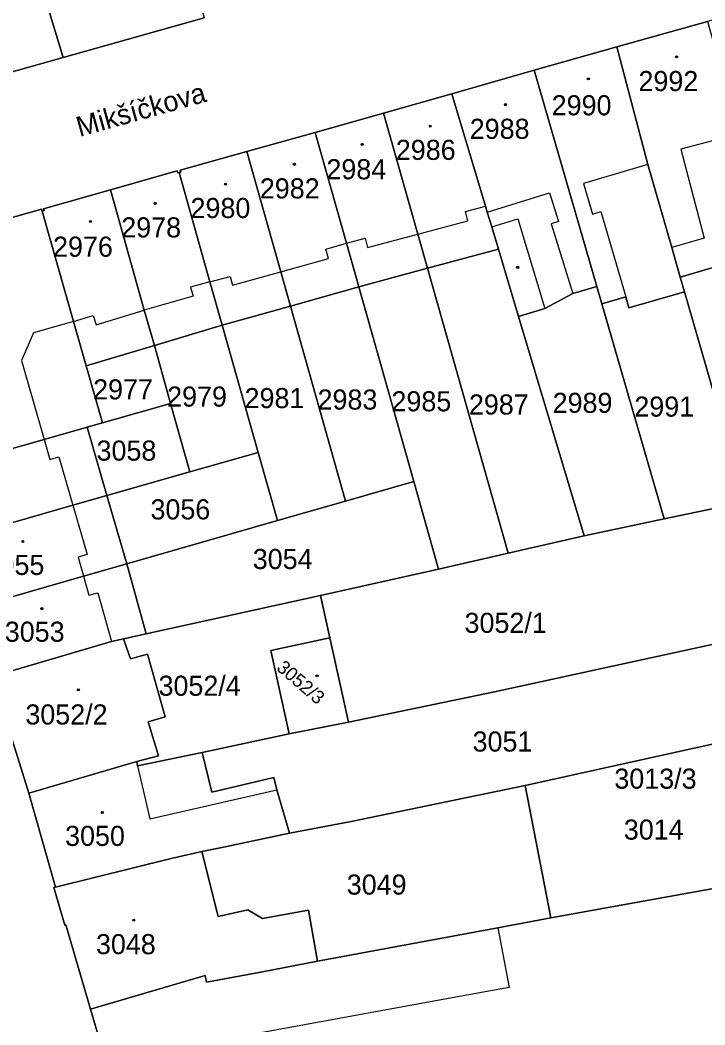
# Model space of a CAD drawing. Extents: x -596233 to -595156, y -1161235 to -1159375.
# Drawn here: x -595507.7 to -595449.8, y -1160793.7 to -1160708.7 of the extents above; entities that cross this region are included whole.
import ezdxf

# ---------------------------------------------------------------- set-up
doc = ezdxf.new("R2010")
doc.units = 0
for name, color, linetype in [('KN_CAR_KR', 7, 'Continuous'), ('KN_KULTURY', 7, 'Continuous'), ('KN_PARC_CIS_POZ', 7, 'Continuous'), ('KN_PARC_CIS_STAV', 7, 'Continuous'), ('KN_PARC_PLOCHA', 7, 'Continuous'), ('KN_ULICE', 7, 'Continuous'), ('parcely_l', 7, 'Continuous')]:
    doc.layers.add(name, color=color, linetype=linetype)

msp = doc.modelspace()

# ---------------------------------------------------------------- linework, layer by layer
at = {"layer": 'KN_CAR_KR'}
for points in [[(-595446.9, -1160718.37), (-595451.84, -1160719.66)], [(-595451.84, -1160719.66), (-595449.87, -1160727.18)], [(-595454.64, -1160720.94), (-595460.07, -1160722.55)], [(-595460.07, -1160722.55), (-595459.31, -1160725.14)], [(-595468.2, -1160724.99), (-595462.94, -1160723.35)], [(-595462.94, -1160723.35), (-595462.19, -1160725.76)], [(-595470.05, -1160724.92), (-595468.35, -1160724.47)], [(-595469.84, -1160725.71), (-595470.05, -1160724.92)], [(-595459.31, -1160725.14), (-595458.6, -1160724.93)], [(-595458.6, -1160724.93), (-595456.49, -1160732.15)], [(-595474.09, -1160726.84), (-595469.84, -1160725.71)], [(-595467.83, -1160726.22), (-595465.63, -1160725.56)], [(-595465.63, -1160725.56), (-595463.35, -1160733.14)], [(-595462.19, -1160725.76), (-595462.81, -1160725.96)], [(-595462.81, -1160725.96), (-595460.97, -1160731.85)], [(-595478.33, -1160727.96), (-595474.09, -1160726.84)], [(-595481.85, -1160728.1), (-595480.11, -1160727.61)], [(-595480.11, -1160727.61), (-595478.54, -1160727.19)], [(-595478.54, -1160727.19), (-595478.33, -1160727.96)], [(-595449.87, -1160727.18), (-595452.6, -1160727.97)], [(-595481.62, -1160728.89), (-595481.85, -1160728.1)], [(-595485.66, -1160730.03), (-595481.62, -1160728.89)], [(-595489.75, -1160731.17), (-595485.66, -1160730.03)], [(-595491.66, -1160730.88), (-595493.29, -1160731.34)], [(-595491.66, -1160730.88), (-595489.96, -1160730.41)], [(-595489.96, -1160730.41), (-595489.75, -1160731.17)], [(-595493.29, -1160731.34), (-595493.08, -1160732.1)], [(-595493.08, -1160732.1), (-595497.21, -1160733.26)], [(-595503.19, -1160734.22), (-595501.52, -1160733.71)], [(-595501.52, -1160733.71), (-595501.27, -1160734.51)], [(-595501.27, -1160734.51), (-595497.21, -1160733.26)], [(-595503.19, -1160734.22), (-595506.58, -1160735.18)], [(-595506.58, -1160735.18), (-595507.58, -1160737.53)], [(-595507.58, -1160737.53), (-595505.69, -1160744.2)], [(-595505.69, -1160744.2), (-595505.2, -1160745.89)], [(-595505.2, -1160745.89), (-595504.44, -1160745.67)], [(-595504.44, -1160745.67), (-595503.25, -1160749.78)], [(-595503.25, -1160749.78), (-595502.05, -1160753.95)], [(-595502.05, -1160753.95), (-595502.81, -1160754.17)], [(-595502.81, -1160754.17), (-595502.35, -1160755.77)], [(-595502.35, -1160755.77), (-595501.9, -1160757.39)], [(-595501.9, -1160757.39), (-595501.15, -1160757.18)], [(-595501.15, -1160757.18), (-595499.99, -1160761.31)], [(-595497.77, -1160771.81), (-595496.74, -1160776.31)], [(-595496.74, -1160776.31), (-595486.01, -1160773.86)], [(-595467.3, -1160785.53), (-595466.36, -1160790.57)], [(-595466.36, -1160790.57), (-595471.79, -1160791.56)], [(-595471.79, -1160791.56), (-595490.59, -1160794.98)]]:
    msp.add_lwpolyline(points, dxfattribs=at)
at = {"layer": 'KN_KULTURY'}
for centre, radius in [((-595452.19, -1160711.84), 0.09), ((-595452.19, -1160711.84), 0.0398), ((-595459.66, -1160713.71), 0.09), ((-595459.66, -1160713.71), 0.0398), ((-595466.66, -1160715.89), 0.09), ((-595466.66, -1160715.89), 0.0398), ((-595473.04, -1160717.71), 0.09), ((-595473.04, -1160717.71), 0.0398), ((-595478.78, -1160719.25), 0.09), ((-595478.78, -1160719.25), 0.0398), ((-595484.52, -1160720.93), 0.09), ((-595484.52, -1160720.93), 0.0398), ((-595490.34, -1160722.61), 0.09), ((-595490.34, -1160722.61), 0.0398), ((-595496.29, -1160724.23), 0.09), ((-595496.29, -1160724.23), 0.0398), ((-595501.76, -1160725.77), 0.09), ((-595501.76, -1160725.77), 0.0398), ((-595465.63, -1160729.65), 0.09), ((-595465.63, -1160729.65), 0.0398), ((-595507.48, -1160752.84), 0.09), ((-595507.48, -1160752.84), 0.0398), ((-595505.87, -1160758.52), 0.09), ((-595505.87, -1160758.52), 0.0398), ((-595482.6, -1160764.21), 0.09), ((-595482.6, -1160764.21), 0.0398), ((-595502.79, -1160765.39), 0.09), ((-595502.79, -1160765.39), 0.0398), ((-595500.76, -1160775.76), 0.09), ((-595500.76, -1160775.76), 0.0398), ((-595498.1, -1160784.87), 0.09), ((-595498.1, -1160784.87), 0.0398)]:
    msp.add_circle(centre, radius, dxfattribs=at)
at = {"layer": 'KN_PARC_PLOCHA'}
for points in [[(-595492.15, -1160708.55), (-595504.07, -1160711.91), (-595506.85, -1160702.69), (-595507.17, -1160701.62), (-595507.5, -1160700.49), (-595505.14, -1160699.84), (-595505.86, -1160697.16), (-595495.96, -1160694.48), (-595495.79, -1160695.2)], [(-595507.5, -1160700.49), (-595507.17, -1160701.62), (-595506.85, -1160702.69), (-595504.07, -1160711.91), (-595522.21, -1160717), (-595524.07, -1160715.97), (-595528.21, -1160701.95), (-595520.99, -1160699.92), (-595520.4, -1160699.75), (-595516.08, -1160698.51), (-595508.65, -1160696.57)], [(-595444.19, -1160728.23), (-595451.88, -1160730.48), (-595452.6, -1160727.97), (-595454.64, -1160720.94), (-595457.25, -1160711.01), (-595449.59, -1160708.86), (-595446.9, -1160718.37)], [(-595451.88, -1160730.48), (-595451.52, -1160731.72), (-595456.22, -1160733.07), (-595456.49, -1160732.15), (-595458.51, -1160732.74), (-595458.94, -1160731.26), (-595464.24, -1160712.98), (-595457.25, -1160711.01), (-595454.64, -1160720.94), (-595452.6, -1160727.97)], [(-595458.94, -1160731.26), (-595460.97, -1160731.85), (-595463.35, -1160733.14), (-595465.56, -1160733.8), (-595467.26, -1160728.11), (-595467.83, -1160726.22), (-595468.2, -1160724.99), (-595468.35, -1160724.47), (-595471.2, -1160714.98), (-595464.24, -1160712.98)], [(-595467.26, -1160728.11), (-595473.27, -1160729.73), (-595474.09, -1160726.84), (-595476.99, -1160716.61), (-595471.2, -1160714.98), (-595468.35, -1160724.47), (-595468.2, -1160724.99), (-595467.83, -1160726.22)], [(-595473.27, -1160729.73), (-595479.07, -1160731.3), (-595480.11, -1160727.61), (-595482.76, -1160718.23), (-595476.99, -1160716.61), (-595474.09, -1160726.84)], [(-595479.07, -1160731.3), (-595484.84, -1160732.92), (-595485.66, -1160730.03), (-595488.53, -1160719.85), (-595482.76, -1160718.23), (-595480.11, -1160727.61)], [(-595484.84, -1160732.92), (-595490.62, -1160734.54), (-595491.66, -1160730.88), (-595494.27, -1160721.63), (-595494.13, -1160721.6), (-595494.17, -1160721.43), (-595488.53, -1160719.85), (-595485.66, -1160730.03)], [(-595494.27, -1160721.63), (-595491.66, -1160730.88), (-595490.62, -1160734.54), (-595496.36, -1160736.25), (-595497.21, -1160733.26), (-595500.07, -1160723.09), (-595494.42, -1160721.49), (-595494.38, -1160721.66)], [(-595496.36, -1160736.25), (-595502.13, -1160737.97), (-595503.19, -1160734.22), (-595505.84, -1160724.89), (-595505.69, -1160724.85), (-595505.74, -1160724.69), (-595500.07, -1160723.09), (-595497.21, -1160733.26)], [(-595505.84, -1160724.89), (-595503.19, -1160734.22), (-595502.13, -1160737.97), (-595500.75, -1160742.81), (-595502.03, -1160743.17), (-595505.69, -1160744.2), (-595514.95, -1160746.83), (-595515.12, -1160746.88), (-595516.33, -1160742.69), (-595516.19, -1160742.65), (-595516.24, -1160742.51), (-595516.37, -1160742.55), (-595520.27, -1160729.28), (-595520.22, -1160729.27), (-595519.92, -1160728.74), (-595519.93, -1160728.69), (-595505.89, -1160724.73)], [(-595465.56, -1160733.8), (-595460, -1160752.35), (-595466.43, -1160753.83), (-595473.27, -1160729.73), (-595467.26, -1160728.11)], [(-595438.59, -1160747.98), (-595446.39, -1160749.49), (-595451.52, -1160731.72), (-595451.88, -1160730.48), (-595444.19, -1160728.23)], [(-595466.43, -1160753.83), (-595472.32, -1160755.18), (-595474.41, -1160747.77), (-595479.07, -1160731.3), (-595473.27, -1160729.73)], [(-595474.41, -1160747.77), (-595480.18, -1160749.42), (-595484.84, -1160732.92), (-595479.07, -1160731.3)], [(-595458.51, -1160732.74), (-595453.24, -1160750.91), (-595460, -1160752.35), (-595465.56, -1160733.8), (-595463.35, -1160733.14), (-595460.97, -1160731.85), (-595458.94, -1160731.26)], [(-595446.39, -1160749.49), (-595449.18, -1160750.07), (-595453.24, -1160750.91), (-595458.51, -1160732.74), (-595456.49, -1160732.15), (-595456.22, -1160733.07), (-595451.52, -1160731.72)], [(-595480.18, -1160749.42), (-595485.95, -1160751.07), (-595487.58, -1160745.3), (-595490.62, -1160734.54), (-595484.84, -1160732.92)], [(-595487.58, -1160745.3), (-595493.35, -1160746.95), (-595494.98, -1160741.17), (-595496.36, -1160736.25), (-595490.62, -1160734.54)], [(-595494.98, -1160741.17), (-595500.75, -1160742.81), (-595502.13, -1160737.97), (-595496.36, -1160736.25)], [(-595493.35, -1160746.95), (-595500.37, -1160748.96), (-595502.03, -1160743.17), (-595500.75, -1160742.81), (-595494.98, -1160741.17)], [(-595500.37, -1160748.96), (-595503.25, -1160749.78), (-595513.43, -1160752.69), (-595515.07, -1160747.05), (-595514.9, -1160747), (-595514.95, -1160746.83), (-595505.69, -1160744.2), (-595502.03, -1160743.17)], [(-595485.95, -1160751.07), (-595498.69, -1160754.72), (-595500.37, -1160748.96), (-595493.35, -1160746.95), (-595487.58, -1160745.3)], [(-595472.32, -1160755.18), (-595482.32, -1160757.4), (-595497.06, -1160760.66), (-595498.69, -1160754.72), (-595485.95, -1160751.07), (-595480.18, -1160749.42), (-595474.41, -1160747.77)], [(-595498.69, -1160754.72), (-595502.35, -1160755.77), (-595511.58, -1160758.41), (-595511.62, -1160758.3), (-595511.79, -1160758.35), (-595513.43, -1160752.69), (-595503.25, -1160749.78), (-595500.37, -1160748.96)], [(-595446.34, -1160760.94), (-595467.6, -1160765.56), (-595479.94, -1160768.13), (-595481.52, -1160760.98), (-595482.32, -1160757.4), (-595472.32, -1160755.18), (-595466.43, -1160753.83), (-595460, -1160752.35), (-595453.24, -1160750.91), (-595449.18, -1160750.07)], [(-595497.06, -1160760.66), (-595498.97, -1160761.08), (-595499.99, -1160761.31), (-595510.08, -1160764.25), (-595511.72, -1160758.58), (-595511.55, -1160758.53), (-595511.58, -1160758.41), (-595502.35, -1160755.77), (-595498.69, -1160754.72)], [(-595481.52, -1160760.98), (-595486.51, -1160762.07), (-595484.95, -1160769.12), (-595492.32, -1160770.7), (-595497.77, -1160771.81), (-595497.85, -1160771.45), (-595496.02, -1160770.96), (-595496.89, -1160768.09), (-595495.44, -1160767.67), (-595496.94, -1160762.36), (-595498.38, -1160762.77), (-595498.97, -1160761.08), (-595497.06, -1160760.66), (-595482.32, -1160757.4)], [(-595497.85, -1160771.45), (-595506.98, -1160774.12), (-595510.08, -1160764.25), (-595499.99, -1160761.31), (-595498.97, -1160761.08), (-595498.38, -1160762.77), (-595496.94, -1160762.36), (-595495.44, -1160767.67), (-595496.89, -1160768.09), (-595496.02, -1160770.96)], [(-595444.33, -1160768.94), (-595448.27, -1160769.8), (-595464.99, -1160773.48), (-595479.71, -1160776.53), (-595484.92, -1160777.52), (-595486.01, -1160773.86), (-595486.26, -1160772.79), (-595491.51, -1160774.03), (-595492.32, -1160770.7), (-595484.95, -1160769.12), (-595479.94, -1160768.13), (-595467.6, -1160765.56), (-595446.34, -1160760.94)], [(-595479.94, -1160768.13), (-595484.95, -1160769.12), (-595486.51, -1160762.07), (-595481.52, -1160760.98)], [(-595443.58, -1160773.21), (-595442.23, -1160780.95), (-595446.26, -1160781.68), (-595462.84, -1160784.68), (-595464.99, -1160773.48), (-595448.27, -1160769.8), (-595447.33, -1160774.04)], [(-595484.92, -1160777.52), (-595490.36, -1160778.68), (-595492.34, -1160779.07), (-595494.93, -1160779.65), (-595504.71, -1160782.07), (-595506.98, -1160774.12), (-595497.85, -1160771.45), (-595497.77, -1160771.81), (-595492.32, -1160770.7), (-595491.51, -1160774.03), (-595486.26, -1160772.79), (-595486.01, -1160773.86)], [(-595462.84, -1160784.68), (-595467.3, -1160785.53), (-595482.56, -1160788.35), (-595483.32, -1160784.03), (-595487.2, -1160784.73), (-595488.46, -1160784.01), (-595490.96, -1160784.56), (-595492.34, -1160779.07), (-595490.36, -1160778.68), (-595484.92, -1160777.52), (-595479.71, -1160776.53), (-595464.99, -1160773.48)], [(-595482.56, -1160788.35), (-595487.2, -1160789.23), (-595491.96, -1160790.12), (-595492.06, -1160789.56), (-595501.75, -1160792.39), (-595503.85, -1160785.26), (-595503.92, -1160785.28), (-595504.86, -1160782.11), (-595504.71, -1160782.07), (-595494.93, -1160779.65), (-595492.34, -1160779.07), (-595490.96, -1160784.56), (-595488.46, -1160784.01), (-595487.2, -1160784.73), (-595483.32, -1160784.03)], [(-595443.6, -1160797.86), (-595449.65, -1160798.7), (-595448.82, -1160804.69), (-595460.14, -1160806.86), (-595464.52, -1160807.85), (-595468.89, -1160808.48), (-595484.58, -1160810.98), (-595485.86, -1160811.18), (-595486.02, -1160810.61), (-595490.72, -1160811.82), (-595495.6, -1160813.26), (-595501.75, -1160792.39), (-595492.06, -1160789.56), (-595491.96, -1160790.12), (-595487.2, -1160789.23), (-595482.56, -1160788.35), (-595467.3, -1160785.53), (-595462.84, -1160784.68), (-595446.26, -1160781.68)]]:
    msp.add_lwpolyline(points, close=True, dxfattribs=at)
for points in [[(-595443.88, -1160707.25), (-595449.59, -1160708.86), (-595457.25, -1160711.01), (-595464.24, -1160712.98), (-595471.2, -1160714.98), (-595476.99, -1160716.61), (-595482.76, -1160718.23), (-595488.53, -1160719.85), (-595494.17, -1160721.43), (-595494.13, -1160721.6), (-595494.27, -1160721.63), (-595494.38, -1160721.66), (-595494.42, -1160721.49), (-595500.07, -1160723.09), (-595505.74, -1160724.69), (-595505.69, -1160724.85), (-595505.84, -1160724.89), (-595505.89, -1160724.73), (-595519.93, -1160728.69)], [(-595522.21, -1160717), (-595504.07, -1160711.91), (-595492.15, -1160708.55)], [(-595510.08, -1160764.25), (-595506.98, -1160774.12), (-595504.71, -1160782.07), (-595504.86, -1160782.11), (-595503.92, -1160785.28), (-595503.85, -1160785.26), (-595501.75, -1160792.39), (-595495.6, -1160813.26)]]:
    msp.add_lwpolyline(points, dxfattribs=at)
at = {"layer": 'parcely_l'}
for points in [[(-595504.07, -1160711.91), (-595506.85, -1160702.69), (-595507.17, -1160701.62), (-595507.5, -1160700.49)], [(-595492.15, -1160708.55), (-595504.07, -1160711.91)], [(-595457.25, -1160711.01), (-595449.59, -1160708.86)], [(-595464.24, -1160712.98), (-595457.25, -1160711.01)], [(-595457.25, -1160711.01), (-595454.64, -1160720.94), (-595452.6, -1160727.97), (-595451.88, -1160730.48)], [(-595522.21, -1160717), (-595504.07, -1160711.91)], [(-595464.24, -1160712.98), (-595471.2, -1160714.98)], [(-595458.94, -1160731.26), (-595464.24, -1160712.98)], [(-595471.2, -1160714.98), (-595476.99, -1160716.61)], [(-595471.2, -1160714.98), (-595468.35, -1160724.47), (-595468.2, -1160724.99), (-595467.83, -1160726.22), (-595467.26, -1160728.11)], [(-595476.99, -1160716.61), (-595482.76, -1160718.23)], [(-595473.27, -1160729.73), (-595474.09, -1160726.84), (-595476.99, -1160716.61)], [(-595488.53, -1160719.85), (-595482.76, -1160718.23)], [(-595482.76, -1160718.23), (-595480.11, -1160727.61), (-595479.07, -1160731.3)], [(-595488.53, -1160719.85), (-595494.17, -1160721.43), (-595494.13, -1160721.6), (-595494.27, -1160721.63)], [(-595484.84, -1160732.92), (-595485.66, -1160730.03), (-595488.53, -1160719.85)], [(-595494.27, -1160721.63), (-595494.38, -1160721.66), (-595494.42, -1160721.49), (-595500.07, -1160723.09)], [(-595490.62, -1160734.54), (-595491.66, -1160730.88), (-595494.27, -1160721.63)], [(-595505.84, -1160724.89), (-595505.69, -1160724.85), (-595505.74, -1160724.69), (-595500.07, -1160723.09)], [(-595500.07, -1160723.09), (-595497.21, -1160733.26), (-595496.36, -1160736.25)], [(-595519.93, -1160728.69), (-595505.89, -1160724.73), (-595505.84, -1160724.89)], [(-595505.84, -1160724.89), (-595503.19, -1160734.22), (-595502.13, -1160737.97)], [(-595467.26, -1160728.11), (-595473.27, -1160729.73)], [(-595467.26, -1160728.11), (-595465.56, -1160733.8)], [(-595451.88, -1160730.48), (-595444.19, -1160728.23)], [(-595479.07, -1160731.3), (-595473.27, -1160729.73)], [(-595473.27, -1160729.73), (-595466.43, -1160753.83)], [(-595451.88, -1160730.48), (-595451.52, -1160731.72)], [(-595479.07, -1160731.3), (-595484.84, -1160732.92)], [(-595474.41, -1160747.77), (-595479.07, -1160731.3)], [(-595465.56, -1160733.8), (-595463.35, -1160733.14), (-595460.97, -1160731.85), (-595458.94, -1160731.26)], [(-595458.51, -1160732.74), (-595458.94, -1160731.26)], [(-595451.52, -1160731.72), (-595456.22, -1160733.07), (-595456.49, -1160732.15), (-595458.51, -1160732.74)], [(-595446.39, -1160749.49), (-595451.52, -1160731.72)], [(-595458.51, -1160732.74), (-595453.24, -1160750.91)], [(-595484.84, -1160732.92), (-595490.62, -1160734.54)], [(-595480.18, -1160749.42), (-595484.84, -1160732.92)], [(-595496.36, -1160736.25), (-595490.62, -1160734.54)], [(-595490.62, -1160734.54), (-595487.58, -1160745.3)], [(-595460, -1160752.35), (-595465.56, -1160733.8)], [(-595496.36, -1160736.25), (-595502.13, -1160737.97)], [(-595494.98, -1160741.17), (-595496.36, -1160736.25)], [(-595502.13, -1160737.97), (-595500.75, -1160742.81)], [(-595500.75, -1160742.81), (-595494.98, -1160741.17)], [(-595493.35, -1160746.95), (-595494.98, -1160741.17)], [(-595500.75, -1160742.81), (-595502.03, -1160743.17)], [(-595502.03, -1160743.17), (-595505.69, -1160744.2), (-595514.95, -1160746.83)], [(-595500.37, -1160748.96), (-595502.03, -1160743.17)], [(-595487.58, -1160745.3), (-595493.35, -1160746.95)], [(-595485.95, -1160751.07), (-595487.58, -1160745.3)], [(-595493.35, -1160746.95), (-595500.37, -1160748.96)], [(-595480.18, -1160749.42), (-595474.41, -1160747.77)], [(-595472.32, -1160755.18), (-595474.41, -1160747.77)], [(-595513.43, -1160752.69), (-595503.25, -1160749.78), (-595500.37, -1160748.96)], [(-595500.37, -1160748.96), (-595498.69, -1160754.72)], [(-595485.95, -1160751.07), (-595480.18, -1160749.42)], [(-595453.24, -1160750.91), (-595449.18, -1160750.07)], [(-595498.69, -1160754.72), (-595485.95, -1160751.07)], [(-595453.24, -1160750.91), (-595460, -1160752.35)], [(-595466.43, -1160753.83), (-595460, -1160752.35)], [(-595466.43, -1160753.83), (-595472.32, -1160755.18)], [(-595498.69, -1160754.72), (-595502.35, -1160755.77), (-595511.58, -1160758.41)], [(-595498.69, -1160754.72), (-595497.06, -1160760.66)], [(-595482.32, -1160757.4), (-595472.32, -1160755.18)], [(-595497.06, -1160760.66), (-595482.32, -1160757.4)], [(-595481.52, -1160760.98), (-595482.32, -1160757.4)], [(-595497.06, -1160760.66), (-595498.97, -1160761.08)], [(-595498.97, -1160761.08), (-595499.99, -1160761.31), (-595510.08, -1160764.25)], [(-595497.85, -1160771.45), (-595496.02, -1160770.96), (-595496.89, -1160768.09), (-595495.44, -1160767.67), (-595496.94, -1160762.36), (-595498.38, -1160762.77), (-595498.97, -1160761.08)], [(-595481.52, -1160760.98), (-595486.51, -1160762.07), (-595484.95, -1160769.12)], [(-595479.94, -1160768.13), (-595481.52, -1160760.98)], [(-595446.34, -1160760.94), (-595467.6, -1160765.56), (-595479.94, -1160768.13)], [(-595510.08, -1160764.25), (-595506.98, -1160774.12)], [(-595479.94, -1160768.13), (-595484.95, -1160769.12)], [(-595484.95, -1160769.12), (-595492.32, -1160770.7)], [(-595464.99, -1160773.48), (-595448.27, -1160769.8)], [(-595497.85, -1160771.45), (-595497.77, -1160771.81), (-595492.32, -1160770.7)], [(-595492.32, -1160770.7), (-595491.51, -1160774.03), (-595486.26, -1160772.79), (-595486.01, -1160773.86), (-595484.92, -1160777.52)], [(-595506.98, -1160774.12), (-595497.85, -1160771.45)], [(-595484.92, -1160777.52), (-595479.71, -1160776.53), (-595464.99, -1160773.48)], [(-595464.99, -1160773.48), (-595462.84, -1160784.68)], [(-595504.71, -1160782.07), (-595506.98, -1160774.12)], [(-595492.34, -1160779.07), (-595490.36, -1160778.68), (-595484.92, -1160777.52)], [(-595492.34, -1160779.07), (-595494.93, -1160779.65), (-595504.71, -1160782.07)], [(-595482.56, -1160788.35), (-595483.32, -1160784.03), (-595487.2, -1160784.73), (-595488.46, -1160784.01), (-595490.96, -1160784.56), (-595492.34, -1160779.07)], [(-595504.71, -1160782.07), (-595504.86, -1160782.11), (-595503.92, -1160785.28), (-595503.85, -1160785.26), (-595501.75, -1160792.39)], [(-595462.84, -1160784.68), (-595446.26, -1160781.68)], [(-595462.84, -1160784.68), (-595467.3, -1160785.53), (-595482.56, -1160788.35)], [(-595501.75, -1160792.39), (-595492.06, -1160789.56), (-595491.96, -1160790.12), (-595487.2, -1160789.23), (-595482.56, -1160788.35)], [(-595501.75, -1160792.39), (-595495.6, -1160813.26)]]:
    msp.add_lwpolyline(points, dxfattribs=at)

# ---------------------------------------------------------------- texts
at = {"layer": 'KN_PARC_CIS_POZ'}
for s, p in [('2977', (-595501.5366, -1160740.82)), ('2979', (-595495.2766, -1160741.43)), ('2981', (-595488.7266, -1160741.56)), ('2983', (-595482.5566, -1160741.68)), ('2985', (-595476.3066, -1160741.83)), ('2987', (-595469.7566, -1160742.1)), ('2989', (-595462.6766, -1160741.96)), ('2991', (-595455.7666, -1160742.28)), ('3058', (-595501.2466, -1160746)), ('3056', (-595496.6866, -1160750.97)), ('3054', (-595488.0366, -1160755.17)), ('3052/1', (-595470.1266, -1160760.57)), ('3052/4', (-595496.0066, -1160765.89)), ('3051', (-595469.4466, -1160770.61)), ('3013/3', (-595457.4566, -1160773.75)), ('3014', (-595456.6566, -1160778.06)), ('3049', (-595480.0866, -1160782.71))]:
    msp.add_text(s, height=1.7, dxfattribs=at).set_placement(p)
at = {"layer": 'KN_PARC_CIS_STAV'}
for s, p in [('2992', (-595455.4166, -1160714.74)), ('2990', (-595462.7566, -1160716.79)), ('2988', (-595469.6866, -1160718.78)), ('2986', (-595475.9366, -1160720.56)), ('2984', (-595481.8066, -1160722.2)), ('2982', (-595487.4366, -1160723.82)), ('2980', (-595493.2966, -1160725.48)), ('2978', (-595499.1566, -1160727.12)), ('2976', (-595504.9266, -1160728.75)), ('3055', (-595510.7166, -1160755.67)), ('3053', (-595509.0066, -1160761.32)), ('3052/2', (-595507.2666, -1160768.32)), ('3050', (-595503.9066, -1160778.59)), ('3048', (-595501.2966, -1160787.75))]:
    msp.add_text(s, height=1.7, dxfattribs=at).set_placement(p)
msp.add_text('3052/3', height=1.14, rotation=319.12613, dxfattribs=at).set_placement((-595486.1023, -1160763.6463))
at = {"layer": 'KN_ULICE'}
msp.add_text('Mikšíčkova', height=1.7, rotation=15.556513, dxfattribs=at).set_placement((-595502.6856, -1160718.6236))

doc.saveas('drawing.dxf')
